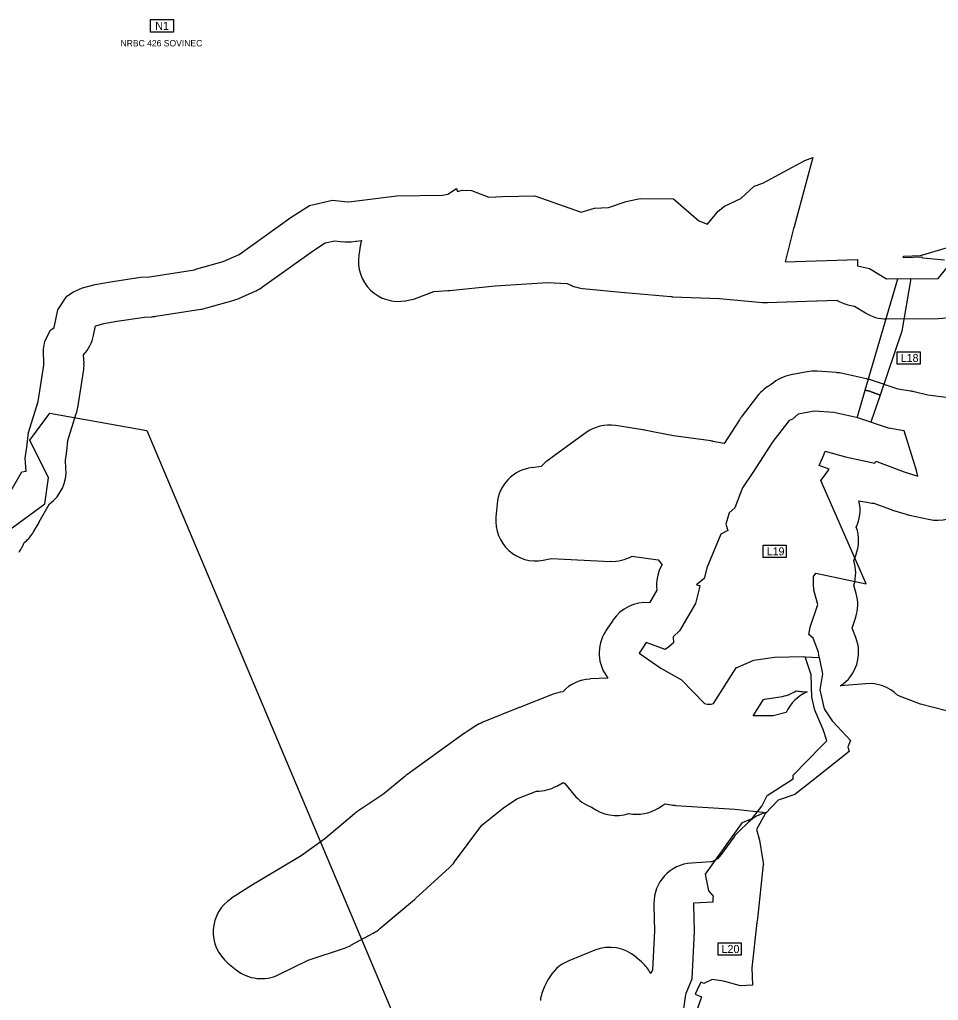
# Model space of a CAD drawing. Extents: x -547623 to -532764, y -1096714 to -1086523.
# Drawn here: x -544729 to -543581, y -1093193 to -1091968 of the extents above; entities that cross this region are included whole.
import ezdxf

# ---------------------------------------------------------------- set-up
doc = ezdxf.new("R2010")
doc.units = 0
for name, color, linetype in [('Vrstva 22', 7, 'Continuous'), ('Vrstva 23', 7, 'Continuous'), ('Vrstva 25', 7, 'Continuous'), ('Vrstva 27', 7, 'Continuous'), ('Vrstva 32', 7, 'Continuous'), ('Vrstva 33', 7, 'Continuous'), ('Vrstva 36', 7, 'Continuous')]:
    doc.layers.add(name, color=color, linetype=linetype)

msp = doc.modelspace()

# ---------------------------------------------------------------- linework, layer by layer
at = {"layer": 'Vrstva 22'}
msp.add_lwpolyline([(-544570.5, -1092481.5), (-544170.3, -1093428.5), (-544273.3, -1093653.1), (-544324, -1093623.3), (-544281.5, -1093528.2), (-544330.2, -1093474.1), (-544403.4, -1093457), (-544439.5, -1093470.8), (-544456.8, -1093510.2), (-544479, -1093516.1), (-544854.9, -1093244.4), (-544828, -1092667.9), (-544697.7, -1092572.9), (-544693.4, -1092540.6), (-544716.6, -1092493.7), (-544691.5, -1092459.6), (-544570.5, -1092481.5)], dxfattribs=at)
at = {"layer": 'Vrstva 23'}
for p, q in [((-544308.4, -1092245), (-544302.3, -1092244.2)), ((-544314.5, -1092245.6), (-544309.3, -1092245.1)), ((-544303.2, -1092248.9), (-544305.4, -1092262.4)), ((-544025.3, -1092303.9), (-543973.5, -1092309)), ((-544494, -1092327.8), (-544461.2, -1092318.5)), ((-544454.7, -1092316.2), (-544434.8, -1092307.4)), ((-544246.9, -1092319.4), (-544241.6, -1092318.4)), ((-543973.1, -1092309), (-543915.6, -1092314.1)), ((-544559.2, -1092338.8), (-544503.1, -1092330)), ((-544497.4, -1092328.7), (-544494.2, -1092327.8)), ((-543794.8, -1092321.6), (-543771.2, -1092320.9)), ((-543771.1, -1092320.9), (-543707.8, -1092318.8)), ((-543645.8, -1092342), (-543581.1, -1092341.6)), ((-544648.9, -1092397.7), (-544649.4, -1092386.8)), ((-544656.8, -1092453.1), (-544649.5, -1092407.7)), ((-543745.3, -1092408.2), (-543765.4, -1092411.9)), ((-543708.5, -1092409.2), (-543732.8, -1092407.5)), ((-543671.1, -1092416.9), (-543701.1, -1092410.2)), ((-543789.6, -1092423.7), (-543790.1, -1092424.2)), ((-543807.2, -1092438.3), (-543827.6, -1092464.8)), ((-543950.7, -1092480.5), (-543984.8, -1092475.3)), ((-544021.8, -1092484.3), (-544035.1, -1092494)), ((-544035.1, -1092494), (-544061.4, -1092513.3)), ((-544061.4, -1092513.3), (-544069.4, -1092519)), ((-544077.5, -1092526.5), (-544089, -1092527.9)), ((-544704.8, -1092595.7), (-544692, -1092572.9)), ((-544132.7, -1092573.1), (-544134.2, -1092589.9)), ((-543662, -1092572.2), (-543641.4, -1092579.9)), ((-543638.7, -1092580.8), (-543621.5, -1092586.1)), ((-543617.3, -1092587.2), (-543593.4, -1092592.4)), ((-544711.9, -1092607.9), (-544705.1, -1092596.3)), ((-544724, -1092621.9), (-544722.4, -1092620.6)), ((-544730.1, -1092633.5), (-544729.4, -1092632.5)), ((-543687, -1092644), (-543684.4, -1092637.4)), ((-543932.9, -1092680.8), (-543942.3, -1092696.6)), ((-543683.8, -1092685.2), (-543686.8, -1092674.6)), ((-543988, -1092718.6), (-543993.3, -1092726.5)), ((-543993.8, -1092727.2), (-543997.1, -1092732.3)), ((-543994.1, -1092790.8), (-544016.3, -1092791.8)), ((-543672, -1092797.7), (-543703.7, -1092800.5)), ((-544062.6, -1092810.9), (-544104.7, -1092827.4)), ((-544105, -1092827.6), (-544150.5, -1092845.9)), ((-544159.1, -1092850.4), (-544171.4, -1092858.4)), ((-544173.3, -1092859.7), (-544245.3, -1092911.6)), ((-543931, -1092953.1), (-543925.4, -1092949.5)), ((-543922.6, -1092947.6), (-543915.1, -1092949)), ((-543818.4, -1092970.7), (-543830.7, -1092982.3)), ((-544234.5, -1093066.1), (-544192.1, -1093027.3)), ((-544435, -1093046.8), (-544464.6, -1093065.8)), ((-544279, -1093103.7), (-544236, -1093067.3)), ((-543936.7, -1093072.7), (-543936.6, -1093075)), ((-544315.3, -1093124.5), (-544287.4, -1093109.4)), ((-544010.4, -1093130.7), (-544043.2, -1093143.9)), ((-543952.2, -1093145.1), (-543959.1, -1093139.2)), ((-544469, -1093146.7), (-544458.8, -1093155)), ((-543940.4, -1093159.9), (-543942, -1093157.2)), ((-544069.2, -1093167.7), (-544073.4, -1093176.1))]:
    msp.add_line(p, q, dxfattribs=at)
for points in [[(-544425.7, -1092302.2), (-544362.3, -1092256.5), (-544347.4, -1092247.1), (-544335.5, -1092244.4), (-544325.4, -1092245.6)], [(-544192, -1092306.5), (-544135.2, -1092300.8), (-544069.6, -1092296.4), (-544044.9, -1092297.8)], [(-544232.5, -1092315.8), (-544211.6, -1092307.7), (-544194.3, -1092306.7)], [(-543913.3, -1092314.3), (-543854.7, -1092316.7), (-543800.8, -1092321.5)], [(-543692.5, -1092324.8), (-543686.2, -1092326.1), (-543672.3, -1092334.6)], [(-544637.1, -1092362.7), (-544634.7, -1092350.9), (-544634.3, -1092350.7), (-544624, -1092347.8), (-544607.7, -1092344.9), (-544573.2, -1092339.8), (-544564, -1092339.3)], [(-543615.9, -1092432.3), (-543631.4, -1092429.9), (-543666.1, -1092418.3)], [(-543571.3, -1092440.4), (-543594.4, -1092437.5), (-543611.6, -1092433.2)], [(-544670.4, -1092507.4), (-544669, -1092493.9), (-544658.5, -1092460.1)], [(-543829.9, -1092468.2), (-543849, -1092497.7), (-543862.9, -1092495)], [(-543865.7, -1092494.5), (-543912.1, -1092488.1), (-543935.8, -1092483.4), (-543948.5, -1092480.9)], [(-544671.5, -1092528.7), (-544672.2, -1092518.4), (-544670.9, -1092510.8)], [(-543680, -1092571.1), (-543680.4, -1092569.1), (-543670.7, -1092571.1)], [(-544075.1, -1092643.4), (-544064.8, -1092641.5), (-543991.3, -1092644.9)], [(-543964.1, -1092638.3), (-543931.2, -1092643.1), (-543926.4, -1092649.1)], [(-543684.4, -1092740), (-543689, -1092728.3), (-543684.5, -1092714.5)], [(-543751.4, -1092807.5), (-543745.1, -1092807.8)], [(-543771.3, -1092833.8), (-543787.6, -1092837.9), (-543812.7, -1092837.7), (-543799.9, -1092817.6), (-543798.3, -1092816.9), (-543778.8, -1092814.1)], [(-543542.8, -1092828.4), (-543571.2, -1092831.5), (-543603.7, -1092823.4), (-543632, -1092812.5)], [(-544247.9, -1092913.6), (-544274.3, -1092935.3), (-544306.5, -1092957)], [(-544058.2, -1092925.7), (-544050.1, -1092921.1), (-544047.9, -1092922.3), (-544036.6, -1092936.2)], [(-544185.7, -1093020.3), (-544151.6, -1092974.6), (-544124.6, -1092952.9), (-544108.1, -1092941.6), (-544083.4, -1092931.9)], [(-543909.2, -1092949.7), (-543835.6, -1092954.3), (-543796.6, -1092958.6)], [(-544310.9, -1092960.4), (-544347.8, -1092991.6), (-544377.6, -1093012.6), (-544433.5, -1093045.9)], [(-543836.9, -1092989.4), (-543852.5, -1093011.1), (-543857.1, -1093016.4), (-543864.4, -1093020.2), (-543865.6, -1093020.3), (-543889.6, -1093021.7)], [(-543936.6, -1093075.1), (-543935.9, -1093106.3), (-543938.5, -1093155.2), (-543940.4, -1093159.9)], [(-544405.3, -1093161), (-544368.8, -1093143.1), (-544323.4, -1093128)]]:
    msp.add_lwpolyline(points, dxfattribs=at)
for centre, start, end in [((-544314.5, -1092195.4), 275.9514, 277.0255), ((-544253.9, -1092256.8), 165.466, 170.9945), ((-544319.7, -1092195.9), 263.4602, 275.9514), ((-544256, -1092270.2), 170.9945, 280.4183), ((-544454.9, -1092261.6), 293.7726, 305.7807), ((-544020.5, -1092254.2), 240.7764, 264.4516), ((-544474.8, -1092270.4), 285.8208, 293.7726), ((-544250.7, -1092269.2), 280.4183, 291.2935), ((-544197, -1092256.8), 273.1861, 275.8061), ((-543968.7, -1092259.2), 264.4516, 264.9125), ((-543911.2, -1092264.3), 264.9125, 267.6436), ((-544510.8, -1092280.6), 278.9134, 285.6356), ((-544507.7, -1092279.7), 285.6356, 285.8208), ((-543796.3, -1092271.7), 264.936, 271.7945), ((-543772.7, -1092270.9), 271.7945, 271.8541), ((-543682.2, -1092275.9), 239.2779, 258.1328), ((-543581.5, -1092291.6), 270.3898, 320.4607), ((-544567, -1092289.4), 273.3665, 278.9134), ((-543646.2, -1092292), 238.4332, 270.3898), ((-544686.1, -1092352.9), 317.315, 348.6155), ((-544698.9, -1092399.8), 350.8428, 2.4251), ((-543756.3, -1092461.1), 100.3801, 131.6791), ((-543736.3, -1092457.4), 86.0782, 100.3801), ((-543711.9, -1092459.1), 77.5076, 86.0782), ((-543767.6, -1092468.8), 116.8142, 142.4345), ((-543681.9, -1092465.7), 71.4894, 77.5076), ((-543623.8, -1092481.7), 75.9034, 81.0229), ((-544706.2, -1092445.2), 342.6274, 350.8428), ((-543787.9, -1092495.3), 142.4345, 147.0991), ((-543992.3, -1092524.7), 81.2766, 126.1323), ((-543958.3, -1092529.9), 78.6814, 81.2766), ((-544005.6, -1092534.4), 126.1323, 126.1489), ((-543872.5, -1092544), 78.8821, 82.2252), ((-544720.2, -1092502.3), 350.1572, 354.1118), ((-544031.9, -1092553.6), 126.1489, 126.1564), ((-544039.9, -1092559.4), 126.1564, 138.7755), ((-544721.3, -1092532.4), 305.91, 4.2978), ((-544082.9, -1092577.5), 96.99, 174.9685), ((-543729, -1092581), 334.9211, 11.3925), ((-543660.5, -1092522.2), 258.2342, 268.2766), ((-543623.9, -1092533), 249.5113, 252.8152), ((-543606.8, -1092538.3), 252.8152, 257.7878), ((-543582.8, -1092543.5), 257.7878, 313.0364), ((-544748.4, -1092571.1), 329.8634, 330.5591), ((-544084.4, -1092594.3), 174.9685, 280.6992), ((-544755.1, -1092582.8), 310.8162, 329.8634), ((-543730.9, -1092618.9), 338.2334, 19.5199), ((-544770.9, -1092604.6), 326.1088, 339.6639), ((-543989, -1092594.9), 267.3565, 299.9467), ((-543883.3, -1092674.4), 149.5127, 187.315), ((-543734.5, -1092659.6), 342.6152, 18.2193), ((-543731.9, -1092698.8), 341.6193, 15.7679), ((-543946.5, -1092746.4), 85.268, 146.1271), ((-543955.1, -1092759.5), 147.0994, 218.7602), ((-543951.8, -1092754.4), 146.1271, 147.0994), ((-543730.8, -1092758.4), 302.8347, 21.6833), ((-544013.9, -1092841.8), 92.7671, 137.2047), ((-544044.3, -1092857.4), 97.2608, 111.4675), ((-543785.8, -1092764.6), 278.0842, 302.7437), ((-543725.5, -1092853.9), 113.0177, 156.3896), ((-543749.1, -1092757.6), 258.7834, 267.3304), ((-543667.7, -1092847.5), 44.4718, 95.0294), ((-544086.4, -1092874), 111.4675, 111.9338), ((-544131.8, -1092892.3), 111.9338, 123.06), ((-544144.1, -1092900.3), 123.06, 125.7772), ((-544216.1, -1092952.1), 125.7772, 129.5172), ((-544082.5, -1092881.9), 268.9776, 299.0576), ((-543997.8, -1092904.7), 219.0928, 250.5648), ((-543983.8, -1092912.4), 232.1685, 288.5998), ((-543957.7, -1092910.8), 258.285, 302.2335), ((-543952.1, -1092907.2), 302.2335, 306.1437), ((-543906.1, -1092899.8), 259.7146, 266.4575), ((-544278.6, -1092998.5), 123.9555, 130.2822), ((-543784, -1093006.9), 104.5844, 133.4699), ((-543796.3, -1093018.6), 133.4699, 144.2569), ((-544225.8, -1092990.4), 312.3757, 323.2277), ((-543886.7, -1093071.6), 93.2657, 181.2241), ((-544407.9, -1093088.8), 120.7788, 122.7372), ((-544437.5, -1093107.9), 122.7372, 230.98), ((-544268.2, -1093029.1), 310.1599, 312.3757), ((-543886.7, -1093073.9), 181.2241, 181.3314), ((-544311.3, -1093065.4), 298.4965, 310.1599), ((-544339.1, -1093080.6), 288.3926, 298.4965), ((-543991.7, -1093177.1), 49.2067, 111.9097), ((-544024.5, -1093190.3), 111.9097, 153.189), ((-543984.9, -1093183), 31.1009, 49.2067), ((-544427.3, -1093116.1), 230.98, 296.1513), ((-544028.8, -1093198.6), 153.189, 173.8588)]:
    msp.add_arc(centre, 50, start, end, dxfattribs=at)
at = {"layer": 'Vrstva 25'}
for points in [[(-544748.4, -1092571.1), (-544726.8, -1092532.9), (-544721.3, -1092532.4), (-544722.6, -1092515.9), (-544720.2, -1092502.3), (-544718.3, -1092483.8), (-544706.2, -1092445.2), (-544698.9, -1092399.8), (-544699.7, -1092379.7), (-544697.7, -1092369.8), (-544690.8, -1092356.1), (-544686.1, -1092352.9), (-544681.7, -1092330.7), (-544670.4, -1092313.6), (-544662, -1092308.1), (-544650.8, -1092303.4), (-544635.1, -1092299), (-544615.8, -1092295.6), (-544578.3, -1092290.1), (-544567, -1092289.4), (-544510.8, -1092280.6), (-544507.7, -1092279.7), (-544474.8, -1092270.4), (-544454.9, -1092261.6), (-544390.2, -1092215), (-544366.9, -1092200.3), (-544338.2, -1092193.8), (-544319.7, -1092195.9), (-544314.5, -1092195.4), (-544257.8, -1092188.4), (-544201, -1092187.6), (-544194.2, -1092186.2), (-544183.5, -1092179.1), (-544182.9, -1092180.9), (-544182.2, -1092183), (-544176, -1092181.2), (-544164.5, -1092181.5), (-544142.9, -1092189.8), (-544125.3, -1092189.3), (-544085.5, -1092188.5), (-544027.4, -1092208.7), (-544010.8, -1092203.7), (-543993.3, -1092202.9), (-543971.4, -1092195.6), (-543954, -1092191.8), (-543912.4, -1092192), (-543880.5, -1092219.7), (-543869.8, -1092223.8), (-543856.2, -1092207.6), (-543848.5, -1092201.2), (-543827.9, -1092191.8), (-543811.3, -1092176.1), (-543800.5, -1092172.6), (-543748.1, -1092144.1), (-543738.2, -1092140.3), (-543761.5, -1092226.9), (-543762.1, -1092229.3), (-543772.7, -1092270.9), (-543682.2, -1092268), (-543682.2, -1092275.9), (-543667.4, -1092279), (-543646.2, -1092292), (-543581.5, -1092291.6), (-543564.7, -1092271.2)], [(-543573.4, -1092268.5), (-543601.2, -1092266.3), (-543601.6, -1092264.8), (-543624.8, -1092265.6), (-543624.8, -1092263.5), (-543603.4, -1092262.9), (-543571, -1092253.1)]]:
    msp.add_lwpolyline(points, dxfattribs=at)
at = {"layer": 'Vrstva 27'}
for points in [[(-544748.4, -1092571.1), (-544726.8, -1092532.9), (-544721.3, -1092532.4), (-544722.6, -1092515.9), (-544720.2, -1092502.3), (-544718.3, -1092483.8), (-544706.2, -1092445.2), (-544698.9, -1092399.8), (-544699.7, -1092379.7), (-544697.7, -1092369.8), (-544690.8, -1092356.1), (-544686.1, -1092352.9), (-544681.7, -1092330.7), (-544670.4, -1092313.6), (-544662, -1092308.1), (-544650.8, -1092303.4), (-544635.1, -1092299), (-544615.8, -1092295.6), (-544578.3, -1092290.1), (-544567, -1092289.4), (-544510.8, -1092280.6), (-544507.7, -1092279.7), (-544474.8, -1092270.4), (-544454.9, -1092261.6), (-544390.2, -1092215), (-544366.9, -1092200.3), (-544338.2, -1092193.8), (-544319.7, -1092195.9), (-544314.5, -1092195.4), (-544257.8, -1092188.4), (-544201, -1092187.6), (-544194.2, -1092186.2), (-544183.5, -1092179.1), (-544182.9, -1092180.9), (-544182.2, -1092183), (-544176, -1092181.2), (-544164.5, -1092181.5), (-544142.9, -1092189.8), (-544125.3, -1092189.3), (-544085.5, -1092188.5), (-544027.4, -1092208.7), (-544010.8, -1092203.7), (-543993.3, -1092202.9), (-543971.4, -1092195.6), (-543954, -1092191.8), (-543912.4, -1092192), (-543880.5, -1092219.7), (-543869.8, -1092223.8), (-543856.2, -1092207.6), (-543848.5, -1092201.2), (-543827.9, -1092191.8), (-543811.3, -1092176.1), (-543800.5, -1092172.6), (-543748.1, -1092144.1), (-543738.2, -1092140.3), (-543761.5, -1092226.9), (-543762.1, -1092229.3), (-543772.7, -1092270.9), (-543682.2, -1092268), (-543682.2, -1092275.9), (-543667.4, -1092279), (-543646.2, -1092292), (-543581.5, -1092291.6), (-543564.7, -1092271.2)], [(-543573.4, -1092268.5), (-543601.2, -1092266.3), (-543601.6, -1092264.8), (-543624.8, -1092265.6), (-543624.8, -1092263.5), (-543603.4, -1092262.9), (-543571, -1092253.1)]]:
    msp.add_lwpolyline(points, dxfattribs=at)
at = {"layer": 'Vrstva 32'}
for p, q in [((-543730.1, -1092764.8), (-543730.8, -1092758.4)), ((-543902, -1092792.9), (-543873.3, -1092822.5))]:
    msp.add_line(p, q, dxfattribs=at)
for points in [[(-543736.3, -1092457.4), (-543756.3, -1092461.1), (-543763.4, -1092467.3), (-543767.6, -1092468.8), (-543787.9, -1092495.3), (-543813, -1092534), (-543826, -1092553.2), (-543829, -1092560.6), (-543835.4, -1092578.2), (-543842.8, -1092584.2), (-543847, -1092598.5), (-543844.4, -1092606.5), (-543853, -1092610.9), (-543868.5, -1092648.2), (-543870.2, -1092651.8)], [(-543681.9, -1092465.7), (-543711.9, -1092459.1), (-543736.3, -1092457.4)], [(-543722.6, -1092507.4), (-543697.4, -1092514.5), (-543660.5, -1092522.2), (-543659.4, -1092519.8), (-543623.9, -1092533), (-543606.8, -1092538.3), (-543608.6, -1092531.3), (-543623.8, -1092481.7), (-543643.3, -1092478.6), (-543681.9, -1092465.7)], [(-543734.5, -1092659.6), (-543671.3, -1092673), (-543727.9, -1092543.9), (-543721.5, -1092535.1), (-543717.5, -1092529.7), (-543730.1, -1092525.3), (-543724.4, -1092512), (-543722.6, -1092507.4)], [(-543870.2, -1092651.8), (-543873.7, -1092666.2), (-543883.3, -1092674.4), (-543879.3, -1092675.2), (-543880.3, -1092679.1), (-543884.7, -1092697.4), (-543904.9, -1092731.5), (-543912.8, -1092739.2), (-543912.3, -1092746.7), (-543918.4, -1092752), (-543922.5, -1092755), (-543946.5, -1092746.4), (-543951.8, -1092754.4)], [(-543737.4, -1092673.1), (-543737.3, -1092663.8), (-543734.5, -1092659.6)], [(-543730.8, -1092758.4), (-543737.8, -1092740.9), (-543743.1, -1092736.2), (-543741.4, -1092727.3), (-543731.9, -1092698.8), (-543737, -1092680.9), (-543737.4, -1092673.1)], [(-543951.8, -1092754.4), (-543955.1, -1092759.5), (-543927.9, -1092778.4), (-543902, -1092792.9)], [(-543873.3, -1092822.5), (-543870, -1092823.2), (-543865.2, -1092823.4), (-543862.3, -1092822.6), (-543833.9, -1092777.9), (-543812, -1092768.3), (-543785.8, -1092764.6)], [(-543785.8, -1092764.6), (-543750.3, -1092763.9), (-543747.6, -1092764.1), (-543747.5, -1092764.1), (-543730.1, -1092764.8)]]:
    msp.add_lwpolyline(points, dxfattribs=at)
at = {"layer": 'Vrstva 33'}
for points in [[(-543667.3, -1092432.4), (-543672.5, -1092431.1), (-543631.8, -1092291.9), (-543615.4, -1092291.8), (-543626.9, -1092357.2), (-543654.1, -1092437.3), (-543667.3, -1092432.4)], [(-543654.1, -1092437.3), (-543665.6, -1092471.1), (-543681.9, -1092465.7), (-543682.6, -1092465.5), (-543672.5, -1092431.1), (-543667.3, -1092432.4), (-543654.1, -1092437.3)], [(-543735.5, -1092830.6), (-543739.3, -1092814.7), (-543740.3, -1092786.6), (-543747.5, -1092764.1), (-543730.1, -1092764.8), (-543725.9, -1092785.3), (-543729.3, -1092805.5), (-543723.8, -1092829.3), (-543714, -1092844), (-543707.4, -1092851)], [(-543725.5, -1092853.9), (-543735.5, -1092830.6)], [(-543762.5, -1092912), (-543727.8, -1092876), (-543720.4, -1092869.1), (-543724.8, -1092856.1), (-543725.5, -1092853.9)], [(-543707.4, -1092851), (-543691.2, -1092868.5), (-543694.5, -1092876.7), (-543692.6, -1092882.5), (-543739.3, -1092919.4)], [(-543840.8, -1092991.9), (-543825.9, -1092971.2), (-543813.8, -1092966.2), (-543801.6, -1092950.7), (-543795.1, -1092937.2), (-543762.6, -1092916.5), (-543762.5, -1092912)], [(-543739.3, -1092919.4), (-543760.4, -1092936.1), (-543781.5, -1092943.4), (-543797.8, -1092960.1), (-543808.5, -1092979.8), (-543804.7, -1092993.2)], [(-543872.4, -1093035.6), (-543840.8, -1092991.9)], [(-543804.7, -1092993.2), (-543801.1, -1093016.3)], [(-543801.1, -1093016.3), (-543799.9, -1093023.4), (-543800, -1093023.7)], [(-543800, -1093023.7), (-543807.3, -1093090.9), (-543807.9, -1093096.1)], [(-543862.5, -1093065.6), (-543862.3, -1093063.1), (-543867.9, -1093056.6), (-543872.4, -1093035.6)], [(-543862.7, -1093070.2), (-543862.5, -1093065.6)], [(-543896.4, -1093184.2), (-543889, -1093166.5), (-543885.9, -1093107.1), (-543886.7, -1093073.9), (-543886.7, -1093071.6), (-543862.7, -1093070.2)], [(-543807.9, -1093096.1), (-543814.1, -1093152.8), (-543813.4, -1093174.1), (-543828.6, -1093174.9), (-543849.6, -1093169.1), (-543863.8, -1093167), (-543874.1, -1093172), (-543878.2, -1093170.6)], [(-543878.2, -1093170.6), (-543882.5, -1093179.9), (-543885.2, -1093185.6)], [(-543902.7, -1093215.9), (-543900.3, -1093209.5), (-543897, -1093188.8), (-543896.4, -1093184.2)], [(-543885.2, -1093185.6), (-543877.4, -1093188.7)], [(-543877.4, -1093188.7), (-543885.1, -1093211.6)]]:
    msp.add_lwpolyline(points, dxfattribs=at)
at = {"layer": 'Vrstva 36'}
for points in [[(-544565.8, -1091968.2), (-544537.2, -1091968.2), (-544537.2, -1091983.7), (-544565.8, -1091983.7)], [(-543632.5, -1092383.1), (-543603.9, -1092383.1), (-543603.9, -1092398.5), (-543632.5, -1092398.5)], [(-543800, -1092624.7), (-543771.4, -1092624.7), (-543771.4, -1092640.1), (-543800, -1092640.1)], [(-543856.3, -1093121.4), (-543827.7, -1093121.4), (-543827.7, -1093136.9), (-543856.3, -1093136.9)]]:
    msp.add_lwpolyline(points, close=True, dxfattribs=at)

# ---------------------------------------------------------------- texts
for s, height, p in [('N1', 10, (-544559.9, -1091981)), ('NRBC 426 SOVINEC', 8, (-544603.3, -1092001.7)), ('L18', 10, (-543628.3, -1092395.8)), ('L19', 10, (-543795.8, -1092637.4)), ('L20', 10, (-543852.1, -1093134.1))]:
    msp.add_text(s, height=height, dxfattribs=at).set_placement(p)

doc.saveas('drawing.dxf')
